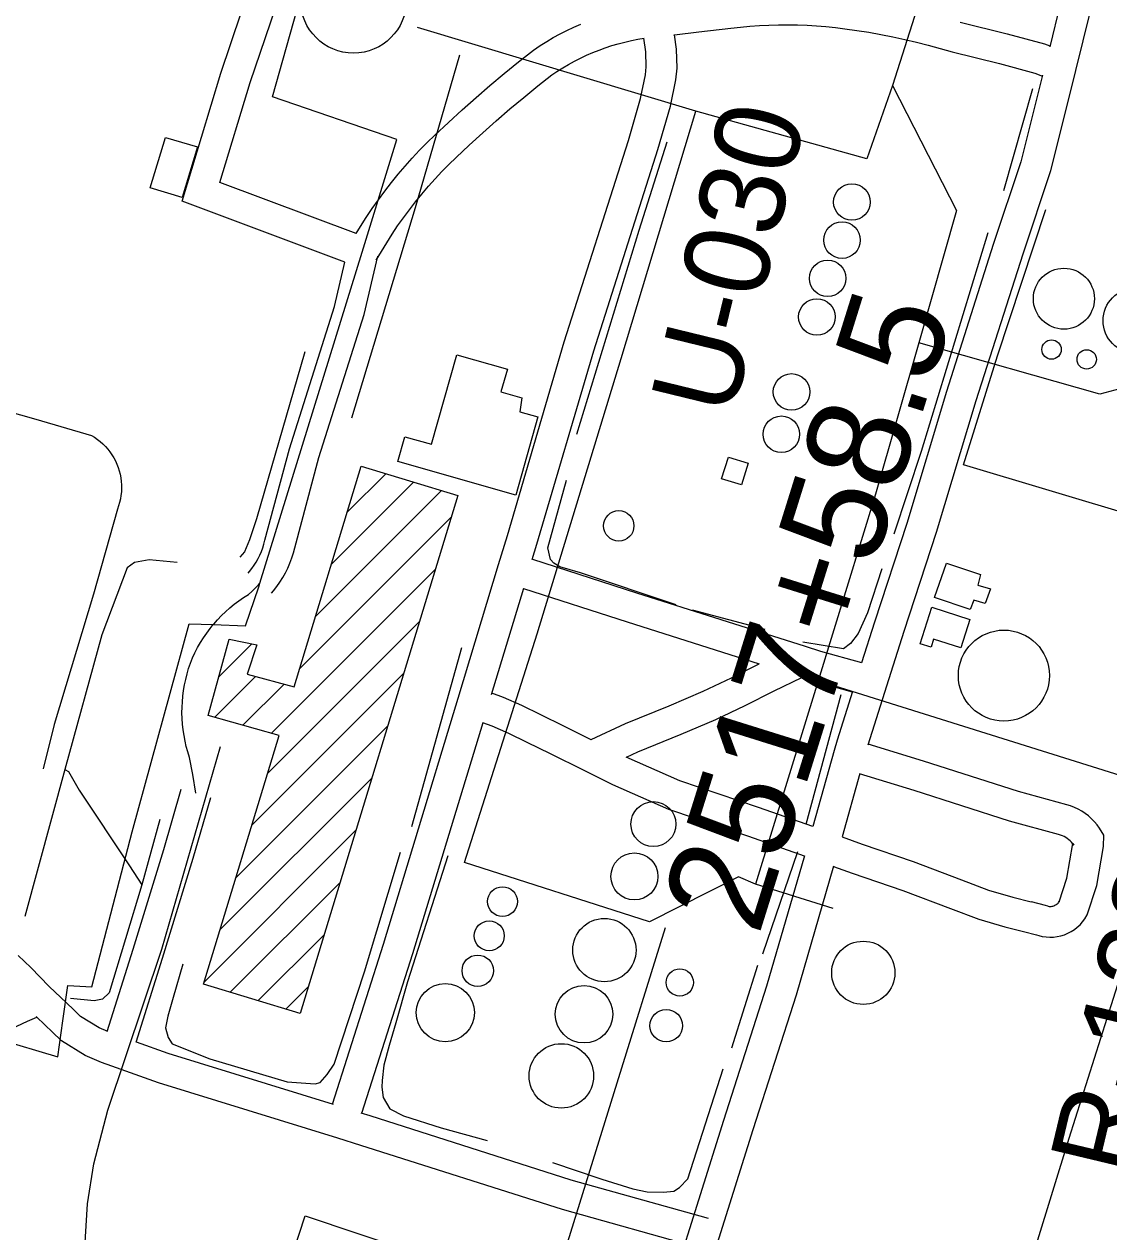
# Model space of a CAD drawing. Extents: x 3535183 to 3573198, y 534952 to 560562.
# Drawn here: x 3557082 to 3558138, y 542641 to 543817 of the extents above; entities that cross this region are included whole.
import ezdxf

# ---------------------------------------------------------------- set-up
doc = ezdxf.new("R2010")
doc.units = 0
for name, color, linetype in [('V-BLDG-OTLN', 7, 'Continuous'), ('V-DOMW-TANK', 7, 'Continuous'), ('V-RIVR-RANG-IDEN', 7, 'Continuous'), ('V-ROAD-CNTR', 7, 'Continuous'), ('V-SITE-OTLN', 7, 'Continuous'), ('V-SURV-IDEN', 7, 'Continuous'), ('V-TOPO-SHOR', 7, 'Continuous'), ('V-UTIL-LINE', 7, 'Continuous')]:
    doc.layers.add(name, color=color, linetype=linetype)

msp = doc.modelspace()

# ---------------------------------------------------------------- linework, layer by layer
at = {"layer": 'V-BLDG-OTLN'}
for p, q in [((3557396.5, 543342.3), (3557433.9, 543379.6)), ((3557381.1, 543291.5), (3557461, 543371.3)), ((3557365.7, 543240.7), (3557488.1, 543363.1)), ((3557350.3, 543189.9), (3557497.8, 543337.5)), ((3557322.4, 543126.7), (3557482.3, 543286.6)), ((3557318.8, 543087.7), (3557466.8, 543235.8)), ((3557271.2, 543181.6), (3557303.4, 543213.8)), ((3557267.4, 543142.4), (3557307.1, 543182.1)), ((3557303.3, 543036.9), (3557451.3, 543184.9)), ((3557294.9, 543134.6), (3557335, 543174.7)), ((3557287.9, 542986.2), (3557435.8, 543134.1)), ((3557272.5, 542935.4), (3557420.3, 543083.2)), ((3557257.1, 542884.6), (3557404.9, 543032.4)), ((3557282.5, 542874.7), (3557389.4, 542981.5)), ((3557309.6, 542866.5), (3557373.9, 542930.7)), ((3557336.7, 542858.2), (3557358.4, 542879.8))]:
    msp.add_line(p, q, dxfattribs=at)
for points in [[(3557204.4, 543657.9), (3557219.3, 543707.1), (3557250.5, 543697.7), (3557235.6, 543648.5)], [(3557582.1, 543434.8), (3557560.6, 543358.8), (3557445.7, 543391.3), (3557452.6, 543415.6), (3557478.6, 543408.2), (3557503.2, 543495.3), (3557552.4, 543481.4), (3557546.1, 543459.4), (3557566.5, 543453.6), (3557564.6, 543439.8)], [(3557786.7, 543389.7), (3557780.2, 543368.6), (3557760.9, 543374.5), (3557767.5, 543395.7)], [(3557504.1, 543358.2), (3557350.5, 542854), (3557256.5, 542882.7), (3557330, 543124.6), (3557260.9, 543144.2), (3557281.5, 543218.5), (3557308.3, 543212.8), (3557299, 543184.3), (3557344.8, 543172.1), (3557410.1, 543386.8)], [(3558013, 543281.3), (3558010.4, 543271.2), (3558022.8, 543267.6), (3558017.4, 543253.2), (3558006.6, 543256.5), (3558002.8, 543247.2), (3557968.1, 543259.1), (3557980, 543292.6)], [(3558002.5, 543237.7), (3557993.7, 543210.1), (3557967.4, 543218.5), (3557964.9, 543210.6), (3557954.3, 543214), (3557965.6, 543249.5)]]:
    msp.add_lwpolyline(points, close=True, dxfattribs=at)
at = {"layer": 'V-DOMW-TANK'}
for centre, radius in [((3557402.5, 543840.6), 51.5), ((3557887.8, 543644.1), 17.8), ((3557878.2, 543607), 17.8), ((3557864.2, 543569.8), 17.8), ((3558094.2, 543550), 29.7), ((3558163.9, 543528.6), 31.6), ((3557853.7, 543532.2), 17.8), ((3558082.2, 543500.5), 9.43), ((3558116.4, 543490.9), 9.42), ((3557829, 543459.2), 17.8), ((3557819.1, 543418), 17.8), ((3557660.8, 543328.8), 14.8), ((3558035.8, 543183), 44.3), ((3557694.5, 543038.4), 21.9), ((3557676, 542987.4), 22.9), ((3557547.6, 542962.9), 14.5), ((3557534.7, 542929.6), 14.6), ((3557646.8, 542915.7), 30.8), ((3557898.9, 542893.6), 30.8), ((3557523.5, 542895.6), 15.3), ((3557720.2, 542884.2), 13.2), ((3557491.9, 542854.8), 28.3), ((3557627, 542853.3), 28), ((3557707, 542842.1), 15.8), ((3557604.9, 542793.2), 31.4)]:
    msp.add_circle(centre, radius, dxfattribs=at)
at = {"layer": 'V-ROAD-CNTR'}
for points in [[(3557394.1, 543585.6), (3557235.6, 543645), (3557273.4, 543769.7), (3557303.3, 543858.6), (3557335.6, 543945.2), (3557350.3, 543990.6), (3557361, 544027)], [(3557405.1, 543613.5), (3557272.5, 543663.2), (3557302, 543760.6), (3557331.6, 543848.6), (3557363.9, 543935.3), (3557379, 543981.8), (3557389.8, 544018.6)], [(3558090.5, 543836.9), (3558080.4, 543795.2)], [(3558119.7, 543829.8), (3558105.6, 543772.2), (3558081.2, 543674.6), (3558054.1, 543593.5), (3558008.4, 543450.6), (3557970, 543322.2), (3557938.3, 543225.8), (3557921.5, 543172.8), (3557903.2, 543115.2)], [(3557405.1, 543613.5), (3557409.3, 543620.3), (3557414.9, 543629.1), (3557420.8, 543637.8), (3557426.8, 543646.3), (3557433, 543654.7), (3557439.4, 543663), (3557446, 543671.1), (3557452.8, 543679.1), (3557459.7, 543686.9), (3557466.9, 543694.5), (3557474.2, 543702), (3557481.6, 543709.3), (3557494.9, 543721.7), (3557508.2, 543733.8), (3557521.8, 543745.8), (3557535.4, 543757.5), (3557549.3, 543769.1), (3557563.2, 543780.5), (3557577.7, 543792), (3557584.2, 543796.4), (3557590.6, 543800.4), (3557597, 543804.2), (3557603.6, 543807.8), (3557610.3, 543811.2), (3557617.1, 543814.4), (3557624, 543817.4)], [(3557714.3, 543806.7), (3557715.1, 543806.8), (3557738.8, 543809.8), (3557770, 543813.5), (3557779.3, 543814.5), (3557788.5, 543815.3), (3557797.8, 543816), (3557807, 543816.4), (3557816.3, 543816.7), (3557825.5, 543816.7), (3557834.8, 543816.6), (3557844.1, 543816.2), (3557853.3, 543815.7), (3557862.5, 543815), (3557871.8, 543814), (3557881, 543812.9), (3557892.7, 543811.2), (3557904.4, 543809.4), (3557916, 543807.3), (3557927.6, 543805), (3557939.2, 543802.5), (3557950.7, 543799.8), (3557962.2, 543796.9), (3557973.6, 543793.7), (3557985.4, 543790.3), (3558031.4, 543778.9), (3558065.8, 543769.7), (3558073.3, 543766.7)], [(3557993.2, 543819.2), (3558038.9, 543807.9), (3558075.3, 543798.2), (3558080.6, 543796.1)], [(3557382.1, 542765.6), (3557431.6, 542921.4), (3557499.9, 543146), (3557504.4, 543161), (3557543.7, 543291.1), (3557552.3, 543319.5), (3557607.7, 543507.9), (3557670.2, 543703.9), (3557682.1, 543744.8), (3557686.7, 543767.8), (3557687.6, 543775.7), (3557687.1, 543790.4), (3557685.3, 543803.6)], [(3557424.7, 543587.5), (3557429.7, 543596.1), (3557434.8, 543604.4), (3557440, 543612.7), (3557445.5, 543620.8), (3557451.1, 543628.8), (3557456.9, 543636.6), (3557462.9, 543644.3), (3557469.1, 543651.9), (3557475.4, 543659.4), (3557481.9, 543666.7), (3557488.6, 543673.8), (3557495.4, 543680.8), (3557502.4, 543687.6), (3557515.2, 543699.6), (3557528.3, 543711.5), (3557541.5, 543723.2), (3557554.8, 543734.7), (3557568.4, 543746), (3557582, 543757.2), (3557595.5, 543767.8), (3557600.6, 543771.3), (3557606.2, 543774.8), (3557611.9, 543778.1), (3557617.6, 543781.3), (3557623.5, 543784.3), (3557629.4, 543787.1), (3557635.5, 543789.7), (3557641.6, 543792.1), (3557647.7, 543794.4), (3557654, 543796.4), (3557660.3, 543798.3), (3557666.7, 543799.9), (3557673.1, 543801.4), (3557679.5, 543802.7), (3557685.6, 543803.7)], [(3557576.6, 543296.1), (3557581.1, 543310.9), (3557636.4, 543499.1), (3557698.9, 543695.2), (3557711.3, 543737.6), (3557716.4, 543763.2), (3557717.7, 543774.5), (3557717.1, 543793), (3557715.1, 543806.8)], [(3558073.5, 543767.6), (3558052.3, 543683.1), (3558025.5, 543602.9), (3557979.8, 543459.5), (3557941.4, 543331.1), (3557909.8, 543235), (3557897.2, 543195.5)], [(3557322.7, 543263.2), (3557324.6, 543265.4), (3557327.8, 543269.6), (3557330.8, 543273.9), (3557333.6, 543278.4), (3557336.2, 543283), (3557338.5, 543287.7), (3557340.6, 543292.6), (3557342.5, 543297.5), (3557344.1, 543302.6), (3557345.3, 543307.3), (3557368.9, 543395.5), (3557412.8, 543534.5), (3557426.3, 543591.5)], [(3557299.9, 543282.7), (3557301.3, 543284.3), (3557303.6, 543287.3), (3557305.8, 543290.4), (3557307.8, 543293.6), (3557309.6, 543296.9), (3557311.3, 543300.3), (3557312.8, 543303.8), (3557314.1, 543307.4), (3557315.3, 543311), (3557316.3, 543315), (3557340.1, 543403.9), (3557383.9, 543542.5), (3557394.1, 543585.6)], [(3556910.6, 543488.7), (3556955.6, 543471.2), (3557020.5, 543453), (3557093.3, 543432.7), (3557147.4, 543416.8)], [(3557147.4, 543416.8), (3557150.3, 543415), (3557153.2, 543413), (3557155.9, 543410.9), (3557158.5, 543408.6), (3557160.9, 543406.1), (3557163.2, 543403.5), (3557165.3, 543400.8), (3557167.3, 543398), (3557169.1, 543395), (3557170.7, 543392), (3557172.1, 543388.8), (3557173.4, 543385.6), (3557174.4, 543382.3), (3557175.3, 543379), (3557175.9, 543375.6), (3557176.4, 543372.1), (3557176.6, 543368.7), (3557176.6, 543365.2), (3557176.5, 543361.8), (3557176.1, 543358.4), (3557175.6, 543355), (3557174.8, 543351.6), (3557173.8, 543348.3), (3557172.7, 543345), (3557149.2, 543262.4), (3557111, 543135.5), (3557100.2, 543092.2)], [(3557576.7, 543296.5), (3557678, 543263.7), (3557842.3, 543211.7), (3557857.3, 543206.9), (3557897.3, 543195.7)], [(3557266, 543232.6), (3557266.4, 543233.2), (3557270.1, 543237.3), (3557274, 543241.4), (3557278, 543245.2), (3557282.1, 543248.9), (3557286.4, 543252.5), (3557290.9, 543255.8), (3557295.5, 543259), (3557300.2, 543262), (3557303.6, 543265), (3557306.9, 543268.1), (3557310, 543271.4), (3557311.3, 543272.9)], [(3557536.8, 543164.5), (3557568.2, 543268.2)], [(3557568, 543267.7), (3557668.9, 543235.2), (3557797.5, 543194.4)], [(3557249.1, 543068.4), (3557246, 543086.8), (3557242.8, 543103.4), (3557241.2, 543108.7), (3557239.7, 543114), (3557238.5, 543119.3), (3557237.5, 543124.7), (3557236.7, 543130.2), (3557236.1, 543135.6), (3557235.7, 543141.1), (3557235.5, 543146.6), (3557235.6, 543152.1), (3557235.9, 543157.6), (3557236.4, 543163.1), (3557237.1, 543168.5), (3557238, 543173.9), (3557239.1, 543179.3), (3557240.4, 543184.6), (3557242, 543189.9), (3557243.7, 543195.1), (3557245.6, 543200.3), (3557248, 543205.3), (3557250.6, 543210.2), (3557253.4, 543215.1), (3557256.4, 543219.8), (3557259.6, 543224.4), (3557262.9, 543228.8), (3557266, 543232.6)], [(3557633.9, 543120.7), (3557667.3, 543136.2), (3557709.8, 543153.7), (3557742.9, 543167.7), (3557770.7, 543180.9), (3557797.4, 543194.4)], [(3557668.3, 543103.6), (3557679.3, 543108.7), (3557721.4, 543126.1), (3557755.2, 543140.4), (3557783.9, 543154), (3557812.1, 543168.3), (3557838.9, 543181.3)], [(3557838.2, 543181.5), (3557848.7, 543178.2), (3557888.2, 543167.1)], [(3557634, 543120.6), (3557607.4, 543133.8), (3557585, 543144.7), (3557566.5, 543154), (3557548.4, 543161.6), (3557537.2, 543165.8)], [(3557888.3, 543167.5), (3557873.3, 543120.2), (3557870.5, 543110.1), (3557849.9, 543036.2)], [(3557410.7, 542756.8), (3557460.3, 542912.4), (3557528.6, 543137.3)], [(3557841.7, 543007.3), (3557787.3, 543026.3), (3557709.5, 543052.5), (3557655, 543076.7), (3557627, 543090.6), (3557594.2, 543106.9), (3557571.7, 543117.8), (3557553.9, 543126.7), (3557537.4, 543133.8), (3557528.5, 543137)], [(3557140.1, 542615.1), (3557143.5, 542668.8), (3557149.6, 542707.7), (3557163.2, 542759.8), (3557215.8, 542916.5), (3557272.9, 543113.9)], [(3558054.9, 542933.7), (3558067.5, 542930.6), (3558069.7, 542929.9), (3558073.2, 542929), (3558076.8, 542928.5), (3558080.5, 542928.3), (3558084.1, 542928.4), (3558087.7, 542928.8), (3558091.3, 542929.6), (3558094.7, 542930.7), (3558098.1, 542932.1), (3558101.3, 542933.7), (3558104.4, 542935.7), (3558107.2, 542937.9), (3558109.9, 542940.4), (3558112.3, 542943.1), (3558114.5, 542946), (3558117, 542950.1), (3558126.2, 542978.5), (3558132.7, 543016.7), (3558133, 543027.6), (3558128.9, 543034.3), (3558126.5, 543037.6), (3558124, 543040.7), (3558121.2, 543043.6), (3558118.1, 543046.3), (3558114.9, 543048.8), (3558111.6, 543051), (3558108, 543053), (3558104.4, 543054.7), (3558100.6, 543056.1), (3558097.1, 543057.1), (3558050, 543070.1), (3557957.4, 543099.6), (3557903.5, 543116.1)], [(3557849.9, 543036.2), (3557797, 543054.7), (3557720.4, 543080.5), (3557668.1, 543103.7)], [(3557895.4, 543087.6), (3557878.2, 543025.9)], [(3558062.2, 542962.9), (3558075.9, 542959.4), (3558078.1, 542958.7), (3558079, 542958.5), (3558079.9, 542958.3), (3558080.8, 542958.3), (3558081.8, 542958.3), (3558082.7, 542958.4), (3558083.6, 542958.6), (3558084.5, 542958.9), (3558085.4, 542959.3), (3558086.2, 542959.7), (3558087, 542960.2), (3558087.8, 542960.8), (3558088.5, 542961.4), (3558089.1, 542962.1), (3558089.6, 542962.9), (3558089.5, 542962.7), (3558097, 542985.7), (3558102.8, 543019.6), (3558102.8, 543019.5), (3558103.8, 543017.8), (3558102.8, 543019.3), (3558101.6, 543020.7), (3558100.3, 543022), (3558099, 543023.2), (3558097.5, 543024.3), (3558096, 543025.4), (3558094.4, 543026.2), (3558092.7, 543027), (3558091, 543027.7), (3558088.9, 543028.3), (3558041.4, 543041.3), (3557948.5, 543071), (3557895.3, 543087.2)], [(3557162.8, 542836.5), (3557187.9, 542916.6), (3557217.8, 543013.6), (3557234.7, 543072.5)], [(3557191, 542826), (3557216.6, 542907.7), (3557246.5, 543005.1), (3557263.5, 543064.2)], [(3557878.2, 543026.1), (3557897.9, 543018.8), (3557947.6, 543002.1), (3557994.5, 542984.2), (3558020.8, 542974.2), (3558044.5, 542967.3), (3558062.2, 542962.8)], [(3557841.7, 543007.6), (3557804.7, 542880.7), (3557762.8, 542749.9), (3557729.7, 542644.3), (3557713.2, 542591.7), (3557703.6, 542556.5), (3557687.7, 542498.6), (3557662.5, 542409.7), (3557624.1, 542302.8), (3557488.2, 542349.9)], [(3557870, 542997.3), (3557833.4, 542871.9), (3557791.4, 542740.8), (3557758.3, 542635.3), (3557742, 542583.2), (3557732.5, 542548.6), (3557716.6, 542490.5), (3557691, 542400.5), (3557642.3, 542264.8), (3557478.3, 542321.6)], [(3557869.9, 542997.1), (3557887.9, 542990.5), (3557937.5, 542973.9), (3557983.8, 542956.2), (3558011.3, 542945.8), (3558036.6, 542938.4), (3558054.8, 542933.8)], [(3557706.1, 542937.5), (3557658.8, 542786.1), (3557602, 542603)], [(3557130.1, 542857.5), (3557123.2, 542864.3), (3557106.2, 542880.2), (3557088.3, 542898.8), (3557076.1, 542910.6)], [(3557047.6, 542824.9), (3557050.7, 542828.4), (3557064.3, 542836.9), (3557085, 542846.4), (3557094.1, 542850.4)], [(3557109.1, 542836), (3557102.4, 542842.7), (3557093.5, 542851)], [(3557163.3, 542836.3), (3557155, 542839.9), (3557136.6, 542851.1), (3557130.2, 542857.5)], [(3557740, 542625.4), (3557606, 542663.1), (3557409.8, 542725.6), (3557387.4, 542732.5), (3557212.6, 542786.5), (3557167.3, 542802.6), (3557157.2, 542806.2), (3557141.1, 542813.2), (3557118.1, 542827.3), (3557109.1, 542836)], [(3557383, 542765.3), (3557222.1, 542815), (3557191.1, 542826)], [(3557748.1, 542654.3), (3557614.6, 542691.8), (3557418.8, 542754.3), (3557410, 542757)]]:
    msp.add_lwpolyline(points, dxfattribs=at)
at = {"layer": 'V-SITE-OTLN'}
for p, q in [((3557323.6, 543746.5), (3557371.8, 543917.7)), ((3557444.7, 543705), (3557323.6, 543746.5)), ((3557410.8, 543595.3), (3557444.7, 543705)), ((3557311.3, 543272.9), (3557410.8, 543595.3)), ((3557310.2, 543269.3), (3557311.3, 543272.9)), ((3557297.3, 543231.4), (3557310.2, 543269.3)), ((3557187.1, 543030.8), (3557242.4, 543233.5)), ((3557242.4, 543233.5), (3557266, 543232.6)), ((3557266, 543232.6), (3557297.3, 543231.4)), ((3557147.7, 542879.9), (3557187.1, 543030.8)), ((3557119.6, 542846.8), (3557124.5, 542881.3)), ((3557124.5, 542881.3), (3557147.7, 542879.9)), ((3557114.7, 542811.7), (3557119.6, 542846.8)), ((3557036.4, 542835), (3557114.7, 542811.7))]:
    msp.add_line(p, q, dxfattribs=at)
at = {"layer": 'V-TOPO-SHOR'}
for p, q in [((3558063.7, 543754.4), (3558035.4, 543655)), ((3557803.5, 543227.9), (3557732.6, 543246.6)), ((3557459.2, 543035.9), (3557508, 543210.4)), ((3557843.3, 543038.4), (3557877.3, 543164.7)), ((3557801.2, 542912), (3557835.1, 543011.6)), ((3557771, 542820.6), (3557796.2, 542901))]:
    msp.add_line(p, q, dxfattribs=at)
for points in [[(3557619.9, 543418), (3557680.6, 543616.7), (3557707.9, 543702.6)], [(3558166.5, 543337.2), (3557996.5, 543388.3), (3558029.5, 543494.2), (3558076.7, 543636.8)], [(3558020.2, 543614), (3557955.2, 543401.2), (3557928.5, 543320.8)], [(3557355.2, 543498.3), (3557307.9, 543335.7), (3557301.1, 543315.1), (3557296.4, 543303.6), (3557291.8, 543298.3)], [(3557716.8, 543251.8), (3557623.5, 543283.2), (3557603.5, 543289), (3557597.6, 543292.4), (3557594.3, 543295.9), (3557591.8, 543307.3), (3557610, 543373.2)], [(3557230.7, 543293.2), (3557203.7, 543295.6), (3557189.3, 543293.2), (3557182, 543287.9), (3557157.3, 543222.8), (3557121.5, 543091.4), (3557082.5, 542948.5)], [(3557916.8, 543287.1), (3557903.1, 543244), (3557893.9, 543224), (3557886.4, 543214.1), (3557879.5, 543208.9), (3557839.9, 543215.4)], [(3557121.5, 543091.4), (3557125, 543089.6), (3557135.4, 543071.4), (3557184.3, 542997.6), (3557196.5, 542979.4)], [(3557213.9, 543042.8), (3557196.5, 542979.4), (3557164.7, 542874), (3557158.2, 542867.8), (3557150.1, 542866.2), (3557126.8, 542868.5)], [(3557236.2, 542902.1), (3557226.8, 542869.4), (3557221.7, 542851.4), (3557219.5, 542840.1), (3557222, 542830.6), (3557225.9, 542824.5), (3557262.5, 542809.7), (3557337.8, 542787.4), (3557365.3, 542785.5), (3557370, 542786.7), (3557376.8, 542794.6), (3557383.8, 542804.6), (3557413.1, 542894.5), (3557448.3, 543011.2)], [(3557494.5, 543007.5), (3557455.1, 542884.9), (3557443.6, 542844.9), (3557437.1, 542822.9), (3557432, 542803.6), (3557430.4, 542788.8), (3557430.2, 542782.1), (3557431.4, 542772.1), (3557437.9, 542761.2), (3557451.1, 542754.2), (3557487.8, 542742.7), (3557532.5, 542730.4)], [(3557596.4, 542709), (3557644.4, 542692.6), (3557674.4, 542683.3), (3557688.4, 542680.3), (3557704.5, 542680), (3557714.5, 542681.1), (3557720, 542684.4), (3557728.2, 542692.9), (3557762.3, 542800)]]:
    msp.add_lwpolyline(points, dxfattribs=at)
at = {"layer": 'V-UTIL-LINE'}
for points in [[(3558002.5, 543988.6), (3557950.9, 543831.9), (3557927.3, 543757.7), (3557989.8, 543636), (3557953, 543507), (3557910.9, 543359.5), (3557854.9, 543178), (3557793.8, 542980)], [(3557927.3, 543757.7), (3557902.3, 543686.2), (3557735.8, 543732.5), (3557464.9, 543814.2)], [(3557505.8, 543787), (3557462.7, 543638.5), (3557400.4, 543433.5)], [(3557510.6, 543001), (3557581.5, 543223.7), (3557663.1, 543491.9), (3557735.8, 543732.5)], [(3558553.9, 543343), (3558379.8, 543398), (3558158.4, 543464.7), (3558129.2, 543457), (3557953, 543507)], [(3558450.2, 542996.9), (3558182, 543075.4), (3557854.9, 543178)], [(3558037, 542530.4), (3558099.2, 542732.5), (3558210.2, 543083.1), (3558288.5, 543058)], [(3557869.4, 542956.3), (3557793.8, 542980), (3557777.3, 542987.2), (3557690.7, 542943.3), (3557510.6, 543001)], [(3557224.5, 542220.4), (3557290.3, 542435.9), (3557308.1, 542498.9), (3557337.5, 542602.5), (3557355.3, 542657.1), (3557561.5, 542587.7)]]:
    msp.add_lwpolyline(points, dxfattribs=at)

# ---------------------------------------------------------------- texts
at = {"layer": 'V-RIVR-RANG-IDEN'}
for s, rotation, p in [('U-030', 76.2963, (3557771.8, 543433.3)), ('R-128.7', 76.6015, (3558160.6, 542693))]:
    msp.add_text(s, height=83, rotation=rotation, dxfattribs=at).set_placement(p)
at = {"layer": 'V-SURV-IDEN'}
msp.add_text('2517+58.5', height=100, rotation=72.631, dxfattribs=at).set_placement((3557796.9, 542928.5))

doc.saveas('drawing.dxf')
